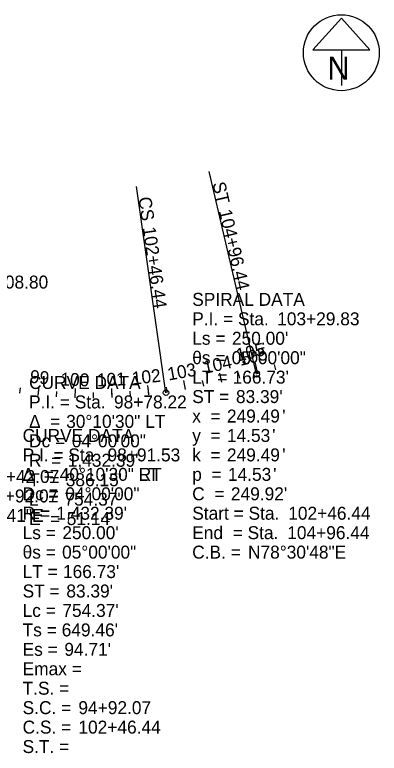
# Model space of a CAD drawing. Extents: x 2000474 to 2003418, y 251807 to 253801.
# Drawn here: x 2002433 to 2003418, y 251807 to 253801 of the extents above; entities that cross this region are included whole.
import ezdxf

# ---------------------------------------------------------------- set-up
doc = ezdxf.new("R2010")
doc.units = 0
for name, color, linetype in [('DV_X_Property_Line', 7, 'Continuous'), ('RW_X_CL_100_Stations', 7, 'Continuous'), ('RW_X_CL_500_Stations', 7, 'Continuous'), ('SC_Scratch1', 7, 'Continuous'), ('SC_Scratch3', 7, 'Continuous'), ('SC_Scratch5', 7, 'Continuous'), ('SC_Shading1', 7, 'Continuous'), ('SH_Text', 7, 'Continuous'), ('TX_X_50', 7, 'Continuous')]:
    doc.layers.add(name, color=color, linetype=linetype)

msp = doc.modelspace()

# ---------------------------------------------------------------- linework, layer by layer
at = {"layer": 'DV_X_Property_Line'}
for p, q in [((2003090.3, 252831.2), (2003082.8, 252863.4)), ((2002992.8, 252808.8), (2002989.6, 252823.5)), ((2002894.8, 252789.1), (2002892.2, 252803.9)), ((2002496.4, 252773.2), (2002497.9, 252788.1)), ((2002596.2, 252766.7), (2002596.9, 252791.7)), ((2002696.2, 252767.3), (2002695.6, 252782.2)), ((2002795.9, 252774.7), (2002794.2, 252789.6))]:
    msp.add_line(p, q, dxfattribs=at)
at = {"layer": 'RW_X_CL_100_Stations'}
for p, q in [((2003086.8, 252830.3), (2002958.8, 253378.1)), ((2002841.9, 252780.6), (2002762.1, 253337.4))]:
    msp.add_line(p, q, dxfattribs=at)
for centre in [(2003086.8, 252830.3), (2002841.9, 252780.6)]:
    msp.add_circle(centre, 7.5, dxfattribs=at)
at = {"layer": 'SC_Scratch1'}
for p, q in [((2003315.8, 253792), (2003238.9, 253706.7)), ((2003392.7, 253706.7), (2003315.8, 253792)), ((2003238.9, 253706.7), (2003392.7, 253706.7)), ((2003315.8, 253706.7), (2003315.8, 253610))]:
    msp.add_line(p, q, dxfattribs=at)
msp.add_circle((2003315.8, 253698.6), 102.5, dxfattribs=at)
at = {"layer": 'SC_Scratch3'}
for p, q in [((2003086.8, 252830.3), (2002958.8, 253378.1)), ((2002841.9, 252780.6), (2002762.1, 253337.4)), ((2003090.3, 252831.2), (2003086.9, 252845.8)), ((2002596.2, 252766.7), (2002596.9, 252791.7))]:
    msp.add_line(p, q, dxfattribs=at)
for centre in [(2003086.8, 252830.3), (2002841.9, 252780.6)]:
    msp.add_circle(centre, 7.5, dxfattribs=at)
at = {"layer": 'SH_Text'}
msp.add_circle((2003315.8, 253698.6), 102.5, dxfattribs=at)
at = {"layer": 'TX_X_50'}
for p, q in [((2003086.8, 252830.3), (2002958.8, 253378.1)), ((2002841.9, 252780.6), (2002762.1, 253337.4)), ((2003090.3, 252831.2), (2003084.6, 252855.5)), ((2003139, 252842.5), (2003135.6, 252857.1)), ((2002992.8, 252808.8), (2002987.5, 252833.2)), ((2003041.6, 252819.8), (2003038.2, 252834.4)), ((2002894.8, 252789.1), (2002890.4, 252813.7)), ((2002943.9, 252798.5), (2002940.9, 252813.2)), ((2002446.7, 252779), (2002448.8, 252793.9)), ((2002496.4, 252773.2), (2002498.9, 252798.1)), ((2002546.2, 252769.1), (2002547.2, 252784.1)), ((2002596.2, 252766.7), (2002596.9, 252791.7)), ((2002696.2, 252767.3), (2002695.1, 252792.2)), ((2002746.1, 252770.1), (2002744.9, 252785.1)), ((2002795.9, 252774.7), (2002793.1, 252799.6)), ((2002845.4, 252781.1), (2002843.3, 252795.9)), ((2002646.2, 252766.1), (2002646.1, 252781.1))]:
    msp.add_line(p, q, dxfattribs=at)
for centre in [(2003086.8, 252830.3), (2002841.9, 252780.6)]:
    msp.add_circle(centre, 7.5, dxfattribs=at)

# ---------------------------------------------------------------- texts
at = {"layer": 'DV_X_Property_Line'}
for s, rotation, p in [('105', 13.1531, (2003035.8, 252864.4)), ('100', 358.2955, (2002556.1, 252799.8))]:
    msp.add_text(s, height=35, rotation=rotation, dxfattribs=at).set_placement(p)
at = {"layer": 'RW_X_CL_100_Stations'}
for s, rotation, p in [('ST', 283.1531, (2002967, 253345.6)), ('CS', 278.1531, (2002767.1, 253307)), ('104+96.44', 283.1531, (2002984.3, 253271.5)), ('102+46.44', 278.1531, (2002778.7, 253226.3))]:
    msp.add_text(s, height=35, rotation=rotation, dxfattribs=at).set_placement(p)
at = {"layer": 'RW_X_CL_500_Stations'}
for s, p in [('94+08.80', (2002327.1, 253061.8)), ('SPIRAL DATA', (2002912.8, 253015.1)), ('P.I. = Sta. ', (2002912.8, 252962.6)), ('103+29.83', (2003142.4, 252962.6)), ('Ls = ', (2002912.8, 252910.1)), ("250.00'", (2003020.2, 252910.1)), ('θs = ', (2002912.8, 252857.6)), ('05°00\'00"', (2003019.5, 252857.6)), ('CURVE DATA', (2002471.8, 252790.6)), ('LT = ', (2002912.8, 252805.1)), ("166.73'", (2003021.9, 252805.1)), ('ST = ', (2002912.8, 252752.6)), ("83.39'", (2003031, 252752.6)), ('P.I. = Sta. ', (2002471.8, 252738.1)), ('98+78.22', (2002701.4, 252738.1)), ('x  = ', (2002912.8, 252700.1)), ('249.49', (2003006.6, 252700.1)), ("'", (2003156, 252700.1)), ('Δ  = ', (2002471.8, 252685.6)), ('30°10\'30" LT', (2002572.1, 252685.6)), ('CURVE DATA', (2002454.4, 252647.6)), ('CURVE DATA', (2002454.4, 252647.6)), ('14.53', (2003006.6, 252647.6)), ("'", (2003128.9, 252647.6)), ('Dc = ', (2002471.8, 252633.1)), ('04°00\'00"', (2002587.3, 252633.1)), ('y  = ', (2002912.8, 252647.6)), ('P.I. = Sta. ', (2002454.4, 252595.1)), ('P.I. = Sta. ', (2002454.4, 252595.1)), ('98+91.53', (2002684, 252595.1)), ('98+91.53', (2002684, 252595.1)), ('k  = ', (2002912.8, 252595.1)), ('249.49', (2003006.6, 252595.1)), ("'", (2003156, 252595.1)), ('R  = ', (2002471.8, 252580.6)), ("1,432.39'", (2002576.4, 252580.6)), ('92+42.07', (2002357, 252536.8)), ('Δ  = ', (2002454.4, 252542.6)), ('Δ  = ', (2002454.4, 252542.6)), ('T  = ', (2002471.8, 252528.1)), ('40°10\'30" LT', (2002554.7, 252542.6)), ('40°10\'30" RT', (2002554.7, 252542.6)), ("386.15'", (2002571, 252528.1)), ('p  = ', (2002912.8, 252542.6)), ('14.53', (2003009.3, 252542.6)), ("'", (2003131.6, 252542.6)), ('Dc = ', (2002454.4, 252490.1)), ('Dc = ', (2002454.4, 252490.1)), ('04°00\'00"', (2002569.9, 252490.1)), ('04°00\'00"', (2002569.9, 252490.1)), ('C  = ', (2002912.8, 252490.1)), ("249.92'", (2003017.4, 252490.1)), ('94+92.07', (2002354.3, 252484.3)), ('L  = ', (2002471.8, 252475.6)), ("754.37'", (2002567.4, 252475.6)), ('S64°38\'41"E', (2002248.3, 252431.8)), ('R = ', (2002454.4, 252437.6)), ('R = ', (2002454.4, 252437.6)), ("1,432.39'", (2002545.4, 252437.6)), ("1,432.39'", (2002545.4, 252437.6)), ('Start = Sta. ', (2002912.8, 252437.6)), ('102+46.44', (2003172.3, 252437.6)), ('E  = ', (2002471.8, 252423.1)), ("51.14'", (2002573.7, 252423.1)), ('Ls = ', (2002454.4, 252385.1)), ('Ls = ', (2002454.4, 252385.1)), ("250.00'", (2002561.8, 252385.1)), ("250.00'", (2002561.8, 252385.1)), ('End  = Sta. ', (2002912.8, 252385.1)), ('104+96.44', (2003169.6, 252385.1)), ('θs = ', (2002454.4, 252332.6)), ('θs = ', (2002454.4, 252332.6)), ('05°00\'00"', (2002561.1, 252332.6)), ('05°00\'00"', (2002561.1, 252332.6)), ('C.B. = ', (2002912.8, 252332.6)), ('N78°30\'48"E', (2003063.6, 252332.6)), ('LT = ', (2002454.4, 252280.1)), ('LT = ', (2002454.4, 252280.1)), ("166.73'", (2002563.5, 252280.1)), ("166.73'", (2002563.5, 252280.1)), ('ST = ', (2002454.4, 252227.6)), ('ST = ', (2002454.4, 252227.6)), ("83.39'", (2002572.6, 252227.6)), ("83.39'", (2002572.6, 252227.6)), ('Lc = ', (2002454.4, 252175.1)), ('Lc = ', (2002454.4, 252175.1)), ("754.37'", (2002561.8, 252175.1)), ("754.37'", (2002561.8, 252175.1)), ('Ts = ', (2002454.4, 252122.6)), ('Ts = ', (2002454.4, 252122.6)), ("649.46'", (2002560, 252122.6)), ("649.46'", (2002560, 252122.6)), ('Es = ', (2002454.4, 252070.1)), ('Es = ', (2002454.4, 252070.1)), ("94.71'", (2002567.2, 252070.1)), ("94.71'", (2002567.2, 252070.1)), ('Emax = ', (2002454.4, 252017.6)), ('Emax = ', (2002454.4, 252017.6)), ('T.S. = ', (2002454.4, 251965.1)), ('T.S. = ', (2002454.4, 251965.1)), ('S.C. = ', (2002454.4, 251912.6)), ('S.C. = ', (2002454.4, 251912.6)), ('94+92.07', (2002605.2, 251912.6)), ('94+92.07', (2002605.2, 251912.6)), ('C.S. = ', (2002454.4, 251860.1)), ('C.S. = ', (2002454.4, 251860.1)), ('102+46.44', (2002605.2, 251860.1)), ('102+46.44', (2002605.2, 251860.1)), ('S.T. = ', (2002454.4, 251807.6)), ('S.T. = ', (2002454.4, 251807.6))]:
    msp.add_text(s, height=35, dxfattribs=at).set_placement(p)
at = {"layer": 'SC_Scratch1'}
msp.add_text('N', height=62.5, dxfattribs=at).set_placement((2003277.9, 253625.8))
at = {"layer": 'SC_Scratch3'}
for s, rotation, p in [('ST', 283.1531, (2002967, 253345.6)), ('CS', 278.1531, (2002767.1, 253307)), ('104+96.44', 283.1531, (2002984.3, 253271.5)), ('102+46.44', 278.1531, (2002778.7, 253226.3)), ('100', 358.2955, (2002556.1, 252799.8))]:
    msp.add_text(s, height=35, rotation=rotation, dxfattribs=at).set_placement(p)
at = {"layer": 'SC_Scratch5'}
for s, p in [('94+08.80', (2002327.1, 253061.8)), ('SPIRAL DATA', (2002912.8, 253015.1)), ('P.I. = Sta. ', (2002912.8, 252962.6)), ('103+29.83', (2003142.4, 252962.6)), ('Ls = ', (2002912.8, 252910.1)), ("250.00'", (2003020.2, 252910.1)), ('θs = ', (2002912.8, 252857.6)), ('05°00\'00"', (2003019.5, 252857.6)), ('CURVE DATA', (2002471.8, 252790.6)), ('LT = ', (2002912.8, 252805.1)), ("166.73'", (2003021.9, 252805.1)), ('ST = ', (2002912.8, 252752.6)), ("83.39'", (2003031, 252752.6)), ('P.I. = Sta. ', (2002471.8, 252738.1)), ('98+78.22', (2002701.4, 252738.1)), ('x  = ', (2002912.8, 252700.1)), ('249.49', (2003006.6, 252700.1)), ("'", (2003156, 252700.1)), ('Δ  = ', (2002471.8, 252685.6)), ('30°10\'30" LT', (2002572.1, 252685.6)), ('CURVE DATA', (2002454.4, 252647.6)), ('CURVE DATA', (2002454.4, 252647.6)), ('14.53', (2003006.6, 252647.6)), ("'", (2003128.9, 252647.6)), ('Dc = ', (2002471.8, 252633.1)), ('04°00\'00"', (2002587.3, 252633.1)), ('y  = ', (2002912.8, 252647.6)), ('P.I. = Sta. ', (2002454.4, 252595.1)), ('P.I. = Sta. ', (2002454.4, 252595.1)), ('98+91.53', (2002684, 252595.1)), ('98+91.53', (2002684, 252595.1)), ('k  = ', (2002912.8, 252595.1)), ('249.49', (2003006.6, 252595.1)), ("'", (2003156, 252595.1)), ('R  = ', (2002471.8, 252580.6)), ("1,432.39'", (2002576.4, 252580.6)), ('92+42.07', (2002357, 252536.8)), ('Δ  = ', (2002454.4, 252542.6)), ('Δ  = ', (2002454.4, 252542.6)), ('T  = ', (2002471.8, 252528.1)), ('40°10\'30" LT', (2002554.7, 252542.6)), ('40°10\'30" RT', (2002554.7, 252542.6)), ("386.15'", (2002571, 252528.1)), ('p  = ', (2002912.8, 252542.6)), ('14.53', (2003009.3, 252542.6)), ("'", (2003131.6, 252542.6)), ('Dc = ', (2002454.4, 252490.1)), ('Dc = ', (2002454.4, 252490.1)), ('04°00\'00"', (2002569.9, 252490.1)), ('04°00\'00"', (2002569.9, 252490.1)), ('C  = ', (2002912.8, 252490.1)), ("249.92'", (2003017.4, 252490.1)), ('94+92.07', (2002354.3, 252484.3)), ('L  = ', (2002471.8, 252475.6)), ("754.37'", (2002567.4, 252475.6)), ('S64°38\'41"E', (2002248.3, 252431.8)), ('R = ', (2002454.4, 252437.6)), ('R = ', (2002454.4, 252437.6)), ("1,432.39'", (2002545.4, 252437.6)), ("1,432.39'", (2002545.4, 252437.6)), ('Start = Sta. ', (2002912.8, 252437.6)), ('102+46.44', (2003172.3, 252437.6)), ('E  = ', (2002471.8, 252423.1)), ("51.14'", (2002573.7, 252423.1)), ('Ls = ', (2002454.4, 252385.1)), ('Ls = ', (2002454.4, 252385.1)), ("250.00'", (2002561.8, 252385.1)), ("250.00'", (2002561.8, 252385.1)), ('End  = Sta. ', (2002912.8, 252385.1)), ('104+96.44', (2003169.6, 252385.1)), ('θs = ', (2002454.4, 252332.6)), ('θs = ', (2002454.4, 252332.6)), ('05°00\'00"', (2002561.1, 252332.6)), ('05°00\'00"', (2002561.1, 252332.6)), ('C.B. = ', (2002912.8, 252332.6)), ('N78°30\'48"E', (2003063.6, 252332.6)), ('LT = ', (2002454.4, 252280.1)), ('LT = ', (2002454.4, 252280.1)), ("166.73'", (2002563.5, 252280.1)), ("166.73'", (2002563.5, 252280.1)), ('ST = ', (2002454.4, 252227.6)), ('ST = ', (2002454.4, 252227.6)), ("83.39'", (2002572.6, 252227.6)), ("83.39'", (2002572.6, 252227.6)), ('Lc = ', (2002454.4, 252175.1)), ('Lc = ', (2002454.4, 252175.1)), ("754.37'", (2002561.8, 252175.1)), ("754.37'", (2002561.8, 252175.1)), ('Ts = ', (2002454.4, 252122.6)), ('Ts = ', (2002454.4, 252122.6)), ("649.46'", (2002560, 252122.6)), ("649.46'", (2002560, 252122.6)), ('Es = ', (2002454.4, 252070.1)), ('Es = ', (2002454.4, 252070.1)), ("94.71'", (2002567.2, 252070.1)), ("94.71'", (2002567.2, 252070.1)), ('Emax = ', (2002454.4, 252017.6)), ('Emax = ', (2002454.4, 252017.6)), ('T.S. = ', (2002454.4, 251965.1)), ('T.S. = ', (2002454.4, 251965.1)), ('S.C. = ', (2002454.4, 251912.6)), ('S.C. = ', (2002454.4, 251912.6)), ('94+92.07', (2002605.2, 251912.6)), ('94+92.07', (2002605.2, 251912.6)), ('C.S. = ', (2002454.4, 251860.1)), ('C.S. = ', (2002454.4, 251860.1)), ('102+46.44', (2002605.2, 251860.1)), ('102+46.44', (2002605.2, 251860.1)), ('S.T. = ', (2002454.4, 251807.6)), ('S.T. = ', (2002454.4, 251807.6))]:
    msp.add_text(s, height=35, dxfattribs=at).set_placement(p)
at = {"layer": 'SC_Shading1'}
for s, p in [('94+08.80', (2002327.1, 253061.8)), ('SPIRAL DATA', (2002912.8, 253015.1)), ('P.I. = Sta. ', (2002912.8, 252962.6)), ('103+29.83', (2003142.4, 252962.6)), ('Ls = ', (2002912.8, 252910.1)), ("250.00'", (2003020.2, 252910.1)), ('θs = ', (2002912.8, 252857.6)), ('05°00\'00"', (2003019.5, 252857.6)), ('CURVE DATA', (2002471.8, 252790.6)), ('LT = ', (2002912.8, 252805.1)), ("166.73'", (2003021.9, 252805.1)), ('ST = ', (2002912.8, 252752.6)), ("83.39'", (2003031, 252752.6)), ('P.I. = Sta. ', (2002471.8, 252738.1)), ('98+78.22', (2002701.4, 252738.1)), ('x  = ', (2002912.8, 252700.1)), ('249.49', (2003006.6, 252700.1)), ("'", (2003156, 252700.1)), ('Δ  = ', (2002471.8, 252685.6)), ('30°10\'30" LT', (2002572.1, 252685.6)), ('CURVE DATA', (2002454.4, 252647.6)), ('CURVE DATA', (2002454.4, 252647.6)), ('14.53', (2003006.6, 252647.6)), ("'", (2003128.9, 252647.6)), ('Dc = ', (2002471.8, 252633.1)), ('04°00\'00"', (2002587.3, 252633.1)), ('y  = ', (2002912.8, 252647.6)), ('P.I. = Sta. ', (2002454.4, 252595.1)), ('P.I. = Sta. ', (2002454.4, 252595.1)), ('98+91.53', (2002684, 252595.1)), ('98+91.53', (2002684, 252595.1)), ('k  = ', (2002912.8, 252595.1)), ('249.49', (2003006.6, 252595.1)), ("'", (2003156, 252595.1)), ('R  = ', (2002471.8, 252580.6)), ("1,432.39'", (2002576.4, 252580.6)), ('92+42.07', (2002357, 252536.8)), ('Δ  = ', (2002454.4, 252542.6)), ('Δ  = ', (2002454.4, 252542.6)), ('T  = ', (2002471.8, 252528.1)), ('40°10\'30" LT', (2002554.7, 252542.6)), ('40°10\'30" RT', (2002554.7, 252542.6)), ("386.15'", (2002571, 252528.1)), ('p  = ', (2002912.8, 252542.6)), ('14.53', (2003009.3, 252542.6)), ("'", (2003131.6, 252542.6)), ('Dc = ', (2002454.4, 252490.1)), ('Dc = ', (2002454.4, 252490.1)), ('04°00\'00"', (2002569.9, 252490.1)), ('04°00\'00"', (2002569.9, 252490.1)), ('C  = ', (2002912.8, 252490.1)), ("249.92'", (2003017.4, 252490.1)), ('94+92.07', (2002354.3, 252484.3)), ('L  = ', (2002471.8, 252475.6)), ("754.37'", (2002567.4, 252475.6)), ('S64°38\'41"E', (2002248.3, 252431.8)), ('R = ', (2002454.4, 252437.6)), ('R = ', (2002454.4, 252437.6)), ("1,432.39'", (2002545.4, 252437.6)), ("1,432.39'", (2002545.4, 252437.6)), ('Start = Sta. ', (2002912.8, 252437.6)), ('102+46.44', (2003172.3, 252437.6)), ('E  = ', (2002471.8, 252423.1)), ("51.14'", (2002573.7, 252423.1)), ('Ls = ', (2002454.4, 252385.1)), ('Ls = ', (2002454.4, 252385.1)), ("250.00'", (2002561.8, 252385.1)), ("250.00'", (2002561.8, 252385.1)), ('End  = Sta. ', (2002912.8, 252385.1)), ('104+96.44', (2003169.6, 252385.1)), ('θs = ', (2002454.4, 252332.6)), ('θs = ', (2002454.4, 252332.6)), ('05°00\'00"', (2002561.1, 252332.6)), ('05°00\'00"', (2002561.1, 252332.6)), ('C.B. = ', (2002912.8, 252332.6)), ('N78°30\'48"E', (2003063.6, 252332.6)), ('LT = ', (2002454.4, 252280.1)), ('LT = ', (2002454.4, 252280.1)), ("166.73'", (2002563.5, 252280.1)), ("166.73'", (2002563.5, 252280.1)), ('ST = ', (2002454.4, 252227.6)), ('ST = ', (2002454.4, 252227.6)), ("83.39'", (2002572.6, 252227.6)), ("83.39'", (2002572.6, 252227.6)), ('Lc = ', (2002454.4, 252175.1)), ('Lc = ', (2002454.4, 252175.1)), ("754.37'", (2002561.8, 252175.1)), ("754.37'", (2002561.8, 252175.1)), ('Ts = ', (2002454.4, 252122.6)), ('Ts = ', (2002454.4, 252122.6)), ("649.46'", (2002560, 252122.6)), ("649.46'", (2002560, 252122.6)), ('Es = ', (2002454.4, 252070.1)), ('Es = ', (2002454.4, 252070.1)), ("94.71'", (2002567.2, 252070.1)), ("94.71'", (2002567.2, 252070.1)), ('Emax = ', (2002454.4, 252017.6)), ('Emax = ', (2002454.4, 252017.6)), ('T.S. = ', (2002454.4, 251965.1)), ('T.S. = ', (2002454.4, 251965.1)), ('S.C. = ', (2002454.4, 251912.6)), ('S.C. = ', (2002454.4, 251912.6)), ('94+92.07', (2002605.2, 251912.6)), ('94+92.07', (2002605.2, 251912.6)), ('C.S. = ', (2002454.4, 251860.1)), ('C.S. = ', (2002454.4, 251860.1)), ('102+46.44', (2002605.2, 251860.1)), ('102+46.44', (2002605.2, 251860.1)), ('S.T. = ', (2002454.4, 251807.6)), ('S.T. = ', (2002454.4, 251807.6))]:
    msp.add_text(s, height=35, dxfattribs=at).set_placement(p)
at = {"layer": 'TX_X_50'}
for s, rotation, p in [('ST', 283.1531, (2002967, 253345.6)), ('CS', 278.1531, (2002767.1, 253307)), ('104+96.44', 283.1531, (2002984.3, 253271.5)), ('102+46.44', 278.1531, (2002778.7, 253226.3)), ('105', 13.1531, (2003043, 252852.8)), ('104', 12.4091, (2002946.4, 252831.2)), ('99', 354.2955, (2002472.6, 252807.6)), ('102', 6.2955, (2002751.7, 252801.9)), ('103', 10.066, (2002849.1, 252813.3)), ('100', 358.2955, (2002556.1, 252799.8)), ('101', 2.2955, (2002656, 252797.5))]:
    msp.add_text(s, height=35, rotation=rotation, dxfattribs=at).set_placement(p)

doc.saveas('drawing.dxf')
